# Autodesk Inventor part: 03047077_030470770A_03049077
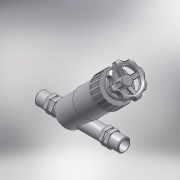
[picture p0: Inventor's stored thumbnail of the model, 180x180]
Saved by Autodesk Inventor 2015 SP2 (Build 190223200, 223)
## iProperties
Created: 2017-05
Part Number: 03047077_030470770A_03049077
Material: Generic
Description: PLASSON ANGLE SEAT VALVE 3/4"-3/4"
Document SubType Name: Modeling
Designer: KIM
Mass: 184.302 g
Surface Area: 375.869 cm^2
Volume: 184.302 cm^3
Density: 1 g/cm^3
Appearance: Default
Author: KIM
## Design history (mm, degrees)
derived "03047.ipt"
feature "Solid1::03047.ipt"
tag "TaggingFeature1"
body "Solid1"
other parameters: "d0" = 151, "d1" = 26.441, "d2" = 27, "d3" = 21.1528, "d4" = 18, "d5" = 18, "d6" = 15.1, "d8" = 1.51, "d12" = 0, "d14" = -7.55, "d15" = 3.02, "d16" = 0, "d17" = 35.937, "d19" = 114.345, "d20" = 43.56, "d21" = 135 deg, "d22" = 46.2825, "d23" = 21.78, "d24" = 51.7275, "d25" = 13.068, "d26" = 90 deg, "d27" = 38.115, "d28" = 70 deg, "d29" = 16.335, "d30" = 13.068, "d31" = 16.335, "d32" = 54.45, "d33" = 38.115, "d34" = 135 deg, "d35" = 2, "d36" = 108.9, "d39" = 52.85, "d40" = 1.21, "d42" = 1, "d43" = 3.63, "d44" = 3.63, "d46" = 0, "d48" = 360 deg, "d50" = 0.605, "d51" = 0.605, "d53" = 360 deg, "d69" = 46.2825, "d70" = 3.63, "d71" = 3.63, "d72" = 7.26, "d74" = 0, "d75" = 0.605, "d77" = 360 deg, "d80" = 50.17567, "d81" = 4.84, "d82" = 2.42, "d83" = 19.602, "d84" = 0, "d86" = 360 deg, "d88" = 1.21, "d89" = 4.356, "d90" = 0.605, "d91" = 121, "H_" = 151, "R_" = 26.441, "E_" = 27, "l_2" = 18, "A_" = 121, "d13" = 15.1, "d67" = 54.45, "d68" = 38.115, "d79" = 51.7275
